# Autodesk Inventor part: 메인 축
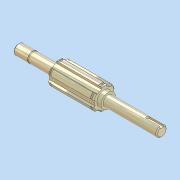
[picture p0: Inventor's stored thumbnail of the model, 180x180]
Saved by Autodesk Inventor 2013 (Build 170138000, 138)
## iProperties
Company: 한국ATC센터
Created: 2014-07
Part Number: 메인 축
Document SubType Name: 모델링
Designer: KYOUNG IL JANG
Mass: 21.4462 g
Surface Area: 72.5109 cm^2
Volume: 21.4462 cm^3
Density: 1 g/cm^3
Material: 강철, 연강
변환 표준: STEP AP214IS
파일 이름: C:\Users\SeoGD\Desktop\?쒗뿕\硫붿씤 異?.stp
전처리기: Build: 253, Release: 2010 SP1 - Date: Wed 07/29/2009
전송 단위: 밀리미터
불확실성: 0.01
Author: KYOUNG IL JANG
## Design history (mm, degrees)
sketch "스케치1"
  geometry: L1 (-69.5, 0)-(69.5, 0); L2 (69.5, 0)-(69.5, 5); L3 (69.5, 5)-(55.5, 5); L4 (55.5, 5)-(55.5, 4.8); L5 (55.5, 4.8)-(54.35, 4.8); L6 (54.35, 4.8)-(54.35, 5); L7 (54.35, 5)-(30.5, 5); L8 (30.5, 5)-(30.5, 9); L9 (30.5, 9)-(-13.5, 9); L10 (-13.5, 9)-(-13.5, 7); L11 (-13.5, 7)-(-17.5, 7); L12 (-17.5, 7)-(-17.5, 5); L13 (-17.5, 5)-(-69.5, 5); L14 (-69.5, 5)-(-69.5, 0); 2 further points
  constraints: 28 end point, 9 parallel, 4 collinear, 2 perpendicular, 1 coincident, 1 horizontal, 1 midpoint
  dimensions: "d2" = 1.15 distance between parallel lines of L6 L4; "d3" = 10 diameter of L3 L1; "d4" = 9.6 diameter of L5 L1; "d6" = 44 distance between parallel lines of L10 L8; "d7" = 4 distance between parallel lines of L12 L10; "d8" = 14 diameter of L11 L1; "d9" = 18 diameter of L9 L1; "d33" = 52 distance from line of L12.end L14; "d37" = 39 distance between parallel lines of L8 L2; "d38" = 14 distance between parallel lines of L2 L4
revolve "회전1" sketch "스케치1" stored, may be unused: angle "d10" = 90 deg
sketch "스케치2"
  geometry: L1 (2.5, 10.712)-(2.5, 8.646); L2 (-2.5, 10.712)-(-2.5, 8.646); A1 r 9 centre (0, 0) between (2.5, 8.646) and (-2.5, 8.646) reference; A2 r 11 centre (0, 0) between (2.5, 10.712) and (-2.5, 10.712); 1 further point
  constraints: 4 end point, 4 point on circle, 2 parallel, 1 centre point, 1 coincident, 1 vertical
  dimensions: "d11" = 22 diameter of A2; "d12" = 5 distance between parallel lines of L1 L2
extrude "돌출1" join sketch "스케치2" stored distance "d13" = 10; taper "d14" = 0 deg
chamfer "모따기1" distance "d15" = 1; stored, may be unused: second distance "d16" = 2, angle "d17" = 45 deg
node "작업 평면1"
node "작업 평면2"
sketch "스케치3"
  geometry: L1 (2.5, 10.712)-(2.5, 10.198); L2 (-2.5, 10.712)-(-2.5, 10.198); A1 r 11 centre (0, 0) between (2.5, 10.712) and (-2.5, 10.712) reference; A2 r 10.5 centre (0, 0) between (2.5, 10.198) and (-2.5, 10.198); 1 further point
  constraints: 4 end point, 2 point on circle, 1 centre point, 1 coincident, 1 parallel, 1 vertical
  dimensions: "d19" = 21 diameter of A2
extrude "돌출2" cut sketch "스케치3" distance "d20" = 1.35; taper "d21" = 0 deg
node "작업 평면3"
sketch "스케치4"
  geometry: L1 (-26, -5)-(-26, 5) reference; L2 (-26, 1.5)-(-12.5, 1.5); L3 (-12.5, -1.5)-(-26, -1.5); A1 r 1.5 centre (-12.5, 0) between (-12.5, -1.5) and (-12.5, 1.5); 2 further points
  constraints: 4 end point, 2 perpendicular, 2 point on circle, 2 point on line, 2 tangent, 1 centre point, 1 horizontal alignment, 1 midpoint
  dimensions: "d25" = 3 distance between parallel lines of L3 L2; "d26" = 15 dimension on A1 L1
extrude "돌출3" cut sketch "스케치4" distance "d27" = 1.8; taper "d28" = 0 deg
chamfer "모따기2" distance "d29" = 1; stored, may be unused: second distance "d30" = 2, angle "d31" = 45 deg
node "솔리드1"
node "솔리드 본체"
node "곡면 본체"
mirror "대칭1"
pattern_circular "원형 패턴1" dims "d23" = 360 deg
node "솔리드2"
other parameters: "d18" = -1.65
